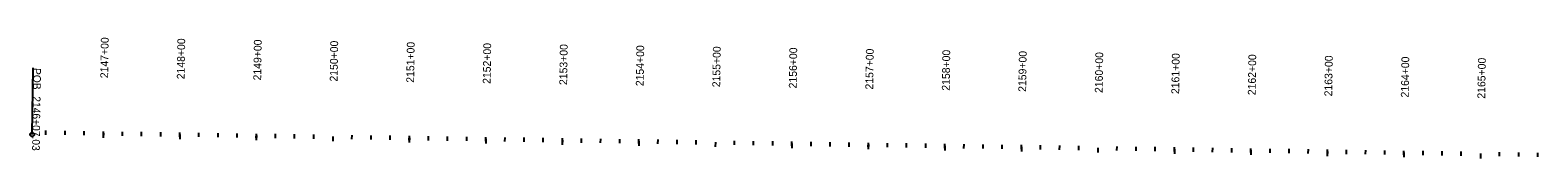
# Model space of a CAD drawing. Extents: x 14295116 to 14303545, y 8637313 to 8653417.
# Drawn here: x 14295116 to 14297086, y 8637625 to 8637783 of the extents above; entities that cross this region are included whole.
import ezdxf

# ---------------------------------------------------------------- set-up
doc = ezdxf.new("R2010")
doc.units = 0
for name, color, linetype in [('CulvertProposed', 7, 'Continuous'), ('Draft_DNC', 7, 'Continuous'), ('G Prop 6 Valve (B1) CELL', 7, 'Continuous')]:
    doc.layers.add(name, color=color, linetype=linetype)

msp = doc.modelspace()

# ---------------------------------------------------------------- linework, layer by layer
at = {"layer": 'CulvertProposed'}
msp.add_line((14295118.4, 8637656.2), (14295119.7, 8637743.2), dxfattribs=at)
msp.add_circle((14295118.4, 8637656.2), 2.67, dxfattribs=at)
at = {"layer": 'Draft_DNC'}
for p, q in [((14295136.4, 8637655.9), (14295136.4, 8637661.4)), ((14295161.4, 8637655.6), (14295161.4, 8637661)), ((14295186.4, 8637655.2), (14295186.4, 8637660.7)), ((14295211.4, 8637657.9), (14295211.3, 8637651.8)), ((14295236.4, 8637654.5), (14295236.4, 8637659.9)), ((14295261.4, 8637654.1), (14295261.4, 8637659.5)), ((14295286.4, 8637653.7), (14295286.4, 8637659.2)), ((14295311.4, 8637656.4), (14295311.3, 8637650.3)), ((14295336.3, 8637653), (14295336.4, 8637658.4)), ((14295361.3, 8637652.6), (14295361.4, 8637658.1)), ((14295386.3, 8637652.2), (14295386.4, 8637657.7)), ((14295411.4, 8637654.9), (14295411.3, 8637648.8)), ((14295436.3, 8637651.5), (14295436.4, 8637656.9)), ((14295461.3, 8637651.1), (14295461.4, 8637656.6)), ((14295486.3, 8637650.7), (14295486.4, 8637656.2)), ((14295511.4, 8637653.4), (14295511.3, 8637647.3)), ((14295536.3, 8637650), (14295536.4, 8637655.5)), ((14295561.3, 8637649.6), (14295561.4, 8637655.1)), ((14295586.3, 8637649.3), (14295586.4, 8637654.7)), ((14295611.4, 8637651.9), (14295611.3, 8637645.8)), ((14295636.3, 8637648.5), (14295636.4, 8637654)), ((14295661.3, 8637648.1), (14295661.4, 8637653.6)), ((14295686.3, 8637647.8), (14295686.4, 8637653.2)), ((14295711.4, 8637650.5), (14295711.3, 8637644.3)), ((14295736.3, 8637647), (14295736.4, 8637652.5)), ((14295761.3, 8637646.7), (14295761.4, 8637652.1)), ((14295786.3, 8637646.3), (14295786.4, 8637651.7)), ((14295811.3, 8637649), (14295811.2, 8637642.9)), ((14295836.3, 8637645.5), (14295836.4, 8637651)), ((14295861.3, 8637645.2), (14295861.4, 8637650.6)), ((14295886.3, 8637644.8), (14295886.4, 8637650.3)), ((14295911.3, 8637647.5), (14295911.2, 8637641.4)), ((14295936.3, 8637644.1), (14295936.4, 8637649.5)), ((14295961.3, 8637643.7), (14295961.4, 8637649.1)), ((14295986.3, 8637643.3), (14295986.4, 8637648.8)), ((14296011.3, 8637646), (14296011.2, 8637639.9)), ((14296036.3, 8637642.6), (14296036.3, 8637648)), ((14296061.3, 8637642.2), (14296061.3, 8637647.7)), ((14296086.3, 8637641.8), (14296086.3, 8637647.3)), ((14296136.3, 8637641.1), (14296136.3, 8637646.5)), ((14296161.3, 8637640.7), (14296161.3, 8637646.2)), ((14296186.3, 8637640.3), (14296186.3, 8637645.8)), ((14296111.3, 8637644.5), (14296111.2, 8637638.4)), ((14296211.3, 8637643), (14296211.2, 8637636.9)), ((14296236.2, 8637639.6), (14296236.3, 8637645.1)), ((14296261.2, 8637639.2), (14296261.3, 8637644.7)), ((14296286.2, 8637638.9), (14296286.3, 8637644.3)), ((14296311.3, 8637641.6), (14296311.2, 8637635.4)), ((14296336.2, 8637638.1), (14296336.3, 8637643.6)), ((14296361.2, 8637637.7), (14296361.3, 8637643.2)), ((14296386.2, 8637637.4), (14296386.3, 8637642.8)), ((14296411.3, 8637640.1), (14296411.2, 8637633.9)), ((14296436.2, 8637636.6), (14296436.3, 8637642.1)), ((14296461.2, 8637636.3), (14296461.3, 8637641.7)), ((14296486.2, 8637635.9), (14296486.3, 8637641.4)), ((14296511.3, 8637638.6), (14296511.2, 8637632.5)), ((14296536.2, 8637635.1), (14296536.3, 8637640.6)), ((14296561.2, 8637634.8), (14296561.3, 8637640.2)), ((14296586.2, 8637634.4), (14296586.3, 8637639.9)), ((14296611.3, 8637637.1), (14296611.2, 8637631)), ((14296636.2, 8637633.7), (14296636.3, 8637639.1)), ((14296661.2, 8637633.3), (14296661.3, 8637638.8)), ((14296686.2, 8637632.9), (14296686.3, 8637638.4)), ((14296711.2, 8637635.6), (14296711.1, 8637629.5)), ((14296736.2, 8637632.2), (14296736.3, 8637637.6)), ((14296761.2, 8637631.8), (14296761.3, 8637637.3)), ((14296786.2, 8637631.4), (14296786.3, 8637636.9)), ((14296811.2, 8637634.1), (14296811.1, 8637628)), ((14296836.2, 8637630.7), (14296836.3, 8637636.2)), ((14296861.2, 8637630.3), (14296861.3, 8637635.8)), ((14296886.2, 8637630), (14296886.3, 8637635.4)), ((14296911.2, 8637632.6), (14296911.1, 8637626.5)), ((14296936.2, 8637629.2), (14296936.3, 8637634.7)), ((14296961.2, 8637628.8), (14296961.2, 8637634.3)), ((14296986.2, 8637628.5), (14296986.2, 8637633.9)), ((14297011.2, 8637631.2), (14297011.1, 8637625)), ((14297036.2, 8637627.7), (14297036.2, 8637633.2)), ((14297061.2, 8637627.4), (14297061.2, 8637632.8)), ((14297086.2, 8637627), (14297086.2, 8637632.4))]:
    msp.add_line(p, q, dxfattribs=at)
at = {"layer": 'G Prop 6 Valve (B1) CELL'}
for p, q in [((14295211.4, 8637654.8), (14295211.4, 8637660.3)), ((14295311.3, 8637653.3), (14295311.4, 8637658.8)), ((14295411.3, 8637651.9), (14295411.4, 8637657.3)), ((14295511.4, 8637653.4), (14295511.3, 8637647.3)), ((14295611.3, 8637648.9), (14295611.4, 8637654.3)), ((14295711.3, 8637647.4), (14295711.4, 8637652.9)), ((14295811.3, 8637645.9), (14295811.4, 8637651.4)), ((14295911.3, 8637644.4), (14295911.4, 8637649.9)), ((14296011.3, 8637646), (14296011.2, 8637639.9)), ((14296111.3, 8637641.5), (14296111.3, 8637646.9)), ((14296211.2, 8637640), (14296211.3, 8637645.4)), ((14296311.2, 8637638.5), (14296311.3, 8637643.9)), ((14296411.2, 8637637), (14296411.3, 8637642.5)), ((14296511.3, 8637638.6), (14296511.2, 8637632.5)), ((14296611.2, 8637634), (14296611.3, 8637639.5)), ((14296711.2, 8637632.6), (14296711.3, 8637638)), ((14296811.2, 8637631.1), (14296811.3, 8637636.5)), ((14296911.2, 8637629.6), (14296911.3, 8637635)), ((14297011.2, 8637631.2), (14297011.1, 8637625))]:
    msp.add_line(p, q, dxfattribs=at)

# ---------------------------------------------------------------- texts
at = {"layer": 'CulvertProposed'}
for s, p in [('POB ', (14295119.9, 8637743.2)), ('2146+07.03', (14295119.3, 8637706.2))]:
    msp.add_text(s, height=10.02, rotation=269.1493, dxfattribs=at).set_placement(p)
at = {"layer": 'Draft_DNC'}
for s, p in [('2147+00', (14295217.6, 8637729.7)), ('2148+00', (14295317.6, 8637728.3)), ('2149+00', (14295417.6, 8637726.8)), ('2150+00', (14295517.5, 8637725.3)), ('2151+00', (14295617.5, 8637723.8)), ('2152+00', (14295717.5, 8637722.3)), ('2153+00', (14295817.5, 8637720.8)), ('2154+00', (14295917.5, 8637719.3)), ('2155+00', (14296017.5, 8637717.9)), ('2156+00', (14296117.5, 8637716.4)), ('2157+00', (14296217.5, 8637714.9)), ('2158+00', (14296317.5, 8637713.4)), ('2159+00', (14296417.4, 8637711.9)), ('2160+00', (14296517.4, 8637710.4)), ('2161+00', (14296617.4, 8637709)), ('2162+00', (14296717.4, 8637707.5)), ('2163+00', (14296817.4, 8637706)), ('2164+00', (14296917.4, 8637704.5)), ('2165+00', (14297017.4, 8637703))]:
    msp.add_text(s, height=10.2, rotation=89.1493, dxfattribs=at).set_placement(p)
at = {"layer": 'G Prop 6 Valve (B1) CELL'}
for s, p in [('2150+00', (14295517.5, 8637725.3)), ('2155+00', (14296017.5, 8637717.9)), ('2160+00', (14296517.4, 8637710.4)), ('2165+00', (14297017.4, 8637703))]:
    msp.add_text(s, height=10.2, rotation=89.1493, dxfattribs=at).set_placement(p)

doc.saveas('drawing.dxf')
